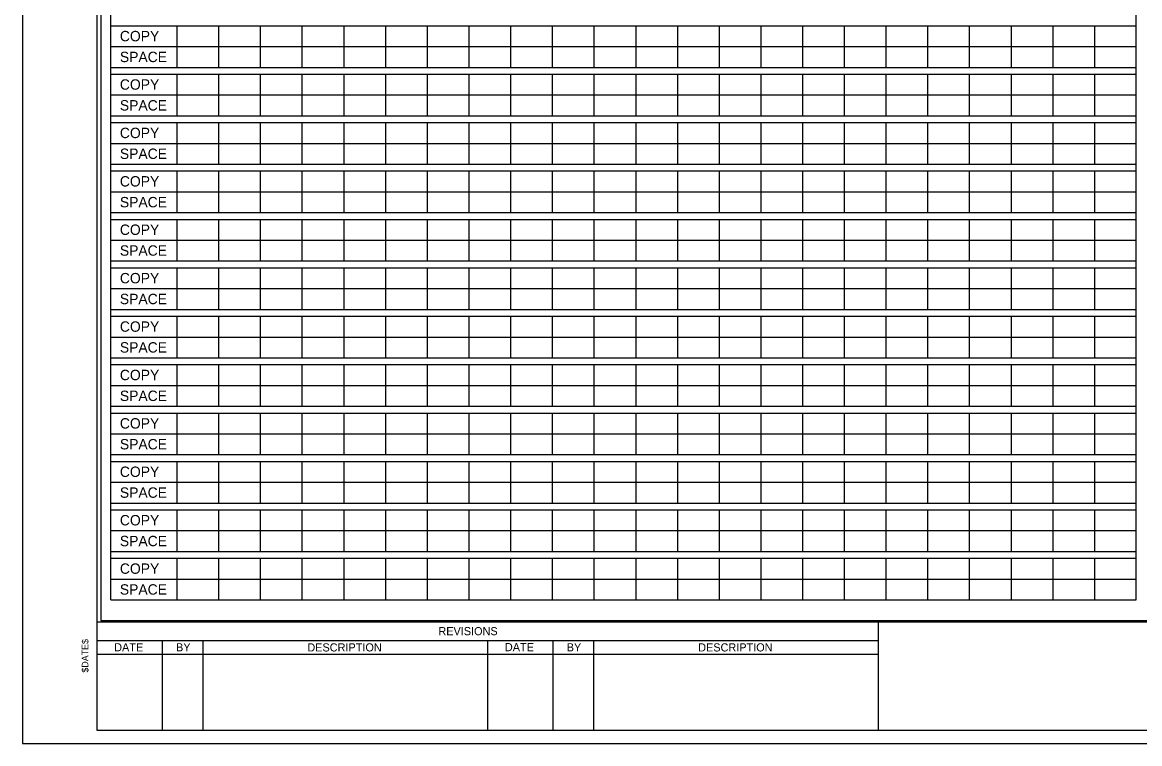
# Model space of a CAD drawing. Extents: x 17890459 to 17890580, y 17897938 to 17898017.
# Drawn here: x 17890458.9 to 17890519.4, y 17897939.5 to 17897978.6 of the extents above; entities that cross this region are included whole.
import ezdxf

# ---------------------------------------------------------------- set-up
doc = ezdxf.new("R2010")
doc.units = 0
for name, color, linetype in [('PlotBorder_dp', 7, 'Continuous'), ('SheetBorder_dp', 7, 'Continuous'), ('SheetLines_dp', 7, 'Continuous'), ('SheetLinesMisc2_dp', 7, 'Continuous'), ('TextMinor', 7, 'Continuous'), ('TextMisc', 7, 'Continuous')]:
    doc.layers.add(name, color=color, linetype=linetype)

msp = doc.modelspace()

# ---------------------------------------------------------------- linework, layer by layer
at = {"layer": 'PlotBorder_dp'}
msp.add_lwpolyline([(17890458.908, 17897939.544), (17890580.045, 17897939.544), (17890580.045, 17898017.365), (17890458.908, 17898017.365)], close=True, dxfattribs=at)
at = {"layer": 'SheetBorder_dp'}
for p, q in [((17890462.946, 17898016.631), (17890462.946, 17897940.278)), ((17890462.946, 17897946.151), (17890576.007, 17897946.151)), ((17890462.946, 17897940.278), (17890576.007, 17897940.278))]:
    msp.add_line(p, q, dxfattribs=at)
at = {"layer": 'SheetLines_dp'}
for p, q in [((17890505.233, 17897946.151), (17890505.233, 17897940.278)), ((17890462.946, 17897945.123), (17890505.233, 17897945.123)), ((17890466.47, 17897945.123), (17890466.47, 17897940.278)), ((17890468.672, 17897945.123), (17890468.672, 17897940.278)), ((17890484.09, 17897945.123), (17890484.09, 17897940.278)), ((17890487.614, 17897945.123), (17890487.614, 17897940.278)), ((17890489.816, 17897945.123), (17890489.816, 17897940.278)), ((17890462.946, 17897944.389), (17890505.233, 17897944.389))]:
    msp.add_line(p, q, dxfattribs=at)
at = {"layer": 'SheetLinesMisc2_dp'}
for p, q in [((17890463.151, 17898016.456), (17890463.151, 17897946.221)), ((17890463.699, 17897947.331), (17890463.699, 17897991.536)), ((17890519.188, 17897947.331), (17890519.188, 17897991.536)), ((17890463.699, 17897978.426), (17890519.188, 17897978.426)), ((17890467.271, 17897978.426), (17890467.271, 17897976.172)), ((17890469.528, 17897978.426), (17890469.528, 17897976.172)), ((17890471.786, 17897978.426), (17890471.786, 17897976.172)), ((17890474.042, 17897978.426), (17890474.042, 17897976.172)), ((17890476.3, 17897978.426), (17890476.3, 17897976.172)), ((17890478.557, 17897978.426), (17890478.557, 17897976.172)), ((17890480.815, 17897978.426), (17890480.815, 17897976.172)), ((17890483.072, 17897978.426), (17890483.072, 17897976.172)), ((17890485.329, 17897978.426), (17890485.329, 17897976.172)), ((17890487.586, 17897978.426), (17890487.586, 17897976.172)), ((17890489.844, 17897978.426), (17890489.844, 17897976.172)), ((17890492.101, 17897978.426), (17890492.101, 17897976.172)), ((17890494.358, 17897978.426), (17890494.358, 17897976.172)), ((17890496.615, 17897978.426), (17890496.615, 17897976.172)), ((17890498.873, 17897978.426), (17890498.873, 17897976.172)), ((17890501.13, 17897978.426), (17890501.13, 17897976.172)), ((17890503.387, 17897978.426), (17890503.387, 17897976.172)), ((17890505.644, 17897978.426), (17890505.644, 17897976.172)), ((17890507.902, 17897978.426), (17890507.902, 17897976.172)), ((17890510.159, 17897978.426), (17890510.159, 17897976.172)), ((17890512.416, 17897978.426), (17890512.416, 17897976.172)), ((17890514.673, 17897978.426), (17890514.673, 17897976.172)), ((17890516.931, 17897978.426), (17890516.931, 17897976.172)), ((17890463.699, 17897977.299), (17890519.188, 17897977.299)), ((17890463.699, 17897976.172), (17890519.188, 17897976.172)), ((17890463.699, 17897975.804), (17890519.188, 17897975.804)), ((17890467.271, 17897975.804), (17890467.271, 17897973.55)), ((17890469.528, 17897975.804), (17890469.528, 17897973.55)), ((17890471.786, 17897975.804), (17890471.786, 17897973.55)), ((17890474.042, 17897975.804), (17890474.042, 17897973.55)), ((17890476.3, 17897975.804), (17890476.3, 17897973.55)), ((17890478.557, 17897975.804), (17890478.557, 17897973.55)), ((17890480.815, 17897975.804), (17890480.815, 17897973.55)), ((17890483.072, 17897975.804), (17890483.072, 17897973.55)), ((17890485.329, 17897975.804), (17890485.329, 17897973.55)), ((17890487.586, 17897975.804), (17890487.586, 17897973.55)), ((17890489.844, 17897975.804), (17890489.844, 17897973.55)), ((17890492.101, 17897975.804), (17890492.101, 17897973.55)), ((17890494.358, 17897975.804), (17890494.358, 17897973.55)), ((17890496.615, 17897975.804), (17890496.615, 17897973.55)), ((17890498.873, 17897975.804), (17890498.873, 17897973.55)), ((17890501.13, 17897975.804), (17890501.13, 17897973.55)), ((17890503.387, 17897975.804), (17890503.387, 17897973.55)), ((17890505.644, 17897975.804), (17890505.644, 17897973.55)), ((17890507.902, 17897975.804), (17890507.902, 17897973.55)), ((17890510.159, 17897975.804), (17890510.159, 17897973.55)), ((17890512.416, 17897975.804), (17890512.416, 17897973.55)), ((17890514.673, 17897975.804), (17890514.673, 17897973.55)), ((17890516.931, 17897975.804), (17890516.931, 17897973.55)), ((17890463.699, 17897974.677), (17890519.188, 17897974.677)), ((17890463.699, 17897973.55), (17890519.188, 17897973.55)), ((17890463.699, 17897973.182), (17890519.188, 17897973.182)), ((17890467.271, 17897973.182), (17890467.271, 17897970.928)), ((17890469.528, 17897973.182), (17890469.528, 17897970.928)), ((17890471.786, 17897973.182), (17890471.786, 17897970.928)), ((17890474.042, 17897973.182), (17890474.042, 17897970.928)), ((17890476.3, 17897973.182), (17890476.3, 17897970.928)), ((17890478.557, 17897973.182), (17890478.557, 17897970.928)), ((17890480.815, 17897973.182), (17890480.815, 17897970.928)), ((17890483.072, 17897973.182), (17890483.072, 17897970.928)), ((17890485.329, 17897973.182), (17890485.329, 17897970.928)), ((17890487.586, 17897973.182), (17890487.586, 17897970.928)), ((17890489.844, 17897973.182), (17890489.844, 17897970.928)), ((17890492.101, 17897973.182), (17890492.101, 17897970.928)), ((17890494.358, 17897973.182), (17890494.358, 17897970.928)), ((17890496.615, 17897973.182), (17890496.615, 17897970.928)), ((17890498.873, 17897973.182), (17890498.873, 17897970.928)), ((17890501.13, 17897973.182), (17890501.13, 17897970.928)), ((17890503.387, 17897973.182), (17890503.387, 17897970.928)), ((17890505.644, 17897973.182), (17890505.644, 17897970.928)), ((17890507.902, 17897973.182), (17890507.902, 17897970.928)), ((17890510.159, 17897973.182), (17890510.159, 17897970.928)), ((17890512.416, 17897973.182), (17890512.416, 17897970.928)), ((17890514.673, 17897973.182), (17890514.673, 17897970.928)), ((17890516.931, 17897973.182), (17890516.931, 17897970.928)), ((17890463.699, 17897972.055), (17890519.188, 17897972.055)), ((17890463.699, 17897970.928), (17890519.188, 17897970.928)), ((17890463.699, 17897970.56), (17890519.188, 17897970.56)), ((17890467.271, 17897970.56), (17890467.271, 17897968.306)), ((17890469.528, 17897970.56), (17890469.528, 17897968.306)), ((17890471.786, 17897970.56), (17890471.786, 17897968.306)), ((17890474.042, 17897970.56), (17890474.042, 17897968.306)), ((17890476.3, 17897970.56), (17890476.3, 17897968.306)), ((17890478.557, 17897970.56), (17890478.557, 17897968.306)), ((17890480.815, 17897970.56), (17890480.815, 17897968.306)), ((17890483.072, 17897970.56), (17890483.072, 17897968.306)), ((17890485.329, 17897970.56), (17890485.329, 17897968.306)), ((17890487.586, 17897970.56), (17890487.586, 17897968.306)), ((17890489.844, 17897970.56), (17890489.844, 17897968.306)), ((17890492.101, 17897970.56), (17890492.101, 17897968.306)), ((17890494.358, 17897970.56), (17890494.358, 17897968.306)), ((17890496.615, 17897970.56), (17890496.615, 17897968.306)), ((17890498.873, 17897970.56), (17890498.873, 17897968.306)), ((17890501.13, 17897970.56), (17890501.13, 17897968.306)), ((17890503.387, 17897970.56), (17890503.387, 17897968.306)), ((17890505.644, 17897970.56), (17890505.644, 17897968.306)), ((17890507.902, 17897970.56), (17890507.902, 17897968.306)), ((17890510.159, 17897970.56), (17890510.159, 17897968.306)), ((17890512.416, 17897970.56), (17890512.416, 17897968.306)), ((17890514.673, 17897970.56), (17890514.673, 17897968.306)), ((17890516.931, 17897970.56), (17890516.931, 17897968.306)), ((17890463.699, 17897969.434), (17890519.188, 17897969.434)), ((17890463.699, 17897968.306), (17890519.188, 17897968.306)), ((17890463.699, 17897967.939), (17890519.188, 17897967.939)), ((17890467.271, 17897967.939), (17890467.271, 17897965.685)), ((17890469.528, 17897967.939), (17890469.528, 17897965.685)), ((17890471.786, 17897967.939), (17890471.786, 17897965.685)), ((17890474.042, 17897967.939), (17890474.042, 17897965.685)), ((17890476.3, 17897967.939), (17890476.3, 17897965.685)), ((17890478.557, 17897967.939), (17890478.557, 17897965.685)), ((17890480.815, 17897967.939), (17890480.815, 17897965.685)), ((17890483.072, 17897967.939), (17890483.072, 17897965.685)), ((17890485.329, 17897967.939), (17890485.329, 17897965.685)), ((17890487.586, 17897967.939), (17890487.586, 17897965.685)), ((17890489.844, 17897967.939), (17890489.844, 17897965.685)), ((17890492.101, 17897967.939), (17890492.101, 17897965.685)), ((17890494.358, 17897967.939), (17890494.358, 17897965.685)), ((17890496.615, 17897967.939), (17890496.615, 17897965.685)), ((17890498.873, 17897967.939), (17890498.873, 17897965.685)), ((17890501.13, 17897967.939), (17890501.13, 17897965.685)), ((17890503.387, 17897967.939), (17890503.387, 17897965.685)), ((17890505.644, 17897967.939), (17890505.644, 17897965.685)), ((17890507.902, 17897967.939), (17890507.902, 17897965.685)), ((17890510.159, 17897967.939), (17890510.159, 17897965.685)), ((17890512.416, 17897967.939), (17890512.416, 17897965.685)), ((17890514.673, 17897967.939), (17890514.673, 17897965.685)), ((17890516.931, 17897967.939), (17890516.931, 17897965.685)), ((17890463.699, 17897966.811), (17890519.188, 17897966.812)), ((17890463.699, 17897965.685), (17890519.188, 17897965.685)), ((17890463.699, 17897965.317), (17890519.188, 17897965.317)), ((17890467.271, 17897965.317), (17890467.271, 17897963.063)), ((17890469.528, 17897965.317), (17890469.528, 17897963.063)), ((17890471.786, 17897965.317), (17890471.786, 17897963.063)), ((17890474.042, 17897965.317), (17890474.042, 17897963.063)), ((17890476.3, 17897965.317), (17890476.3, 17897963.063)), ((17890478.557, 17897965.317), (17890478.557, 17897963.063)), ((17890480.815, 17897965.317), (17890480.815, 17897963.063)), ((17890483.072, 17897965.317), (17890483.072, 17897963.063)), ((17890485.329, 17897965.317), (17890485.329, 17897963.063)), ((17890487.586, 17897965.317), (17890487.586, 17897963.063)), ((17890489.844, 17897965.317), (17890489.844, 17897963.063)), ((17890492.101, 17897965.317), (17890492.101, 17897963.063)), ((17890494.358, 17897965.317), (17890494.358, 17897963.063)), ((17890496.615, 17897965.317), (17890496.615, 17897963.063)), ((17890498.873, 17897965.317), (17890498.873, 17897963.063)), ((17890501.13, 17897965.317), (17890501.13, 17897963.063)), ((17890503.387, 17897965.317), (17890503.387, 17897963.063)), ((17890505.644, 17897965.317), (17890505.644, 17897963.063)), ((17890507.902, 17897965.317), (17890507.902, 17897963.063)), ((17890510.159, 17897965.317), (17890510.159, 17897963.063)), ((17890512.416, 17897965.317), (17890512.416, 17897963.063)), ((17890514.673, 17897965.317), (17890514.673, 17897963.063)), ((17890516.931, 17897965.317), (17890516.931, 17897963.063)), ((17890463.699, 17897964.189), (17890519.188, 17897964.189)), ((17890463.699, 17897963.063), (17890519.188, 17897963.063)), ((17890463.699, 17897962.695), (17890519.188, 17897962.695)), ((17890467.271, 17897962.695), (17890467.271, 17897960.44)), ((17890469.528, 17897962.695), (17890469.528, 17897960.44)), ((17890471.786, 17897962.695), (17890471.786, 17897960.44)), ((17890474.042, 17897962.695), (17890474.042, 17897960.44)), ((17890476.3, 17897962.695), (17890476.3, 17897960.44)), ((17890478.557, 17897962.695), (17890478.557, 17897960.44)), ((17890480.815, 17897962.695), (17890480.815, 17897960.44)), ((17890483.072, 17897962.695), (17890483.072, 17897960.44)), ((17890485.329, 17897962.695), (17890485.329, 17897960.44)), ((17890487.586, 17897962.695), (17890487.586, 17897960.44)), ((17890489.844, 17897962.695), (17890489.844, 17897960.44)), ((17890492.101, 17897962.695), (17890492.101, 17897960.44)), ((17890494.358, 17897962.695), (17890494.358, 17897960.44)), ((17890496.615, 17897962.695), (17890496.615, 17897960.44)), ((17890498.873, 17897962.695), (17890498.873, 17897960.44)), ((17890501.13, 17897962.695), (17890501.13, 17897960.44)), ((17890503.387, 17897962.695), (17890503.387, 17897960.44)), ((17890505.644, 17897962.695), (17890505.644, 17897960.44)), ((17890507.902, 17897962.695), (17890507.902, 17897960.44)), ((17890510.159, 17897962.695), (17890510.159, 17897960.44)), ((17890512.416, 17897962.695), (17890512.416, 17897960.44)), ((17890514.673, 17897962.695), (17890514.673, 17897960.44)), ((17890516.931, 17897962.695), (17890516.931, 17897960.44)), ((17890463.699, 17897961.568), (17890519.188, 17897961.568)), ((17890463.699, 17897960.44), (17890519.188, 17897960.44)), ((17890463.699, 17897960.073), (17890519.188, 17897960.073)), ((17890467.271, 17897960.073), (17890467.271, 17897957.819)), ((17890469.528, 17897960.073), (17890469.528, 17897957.819)), ((17890471.786, 17897960.073), (17890471.786, 17897957.819)), ((17890474.042, 17897960.073), (17890474.042, 17897957.819)), ((17890476.3, 17897960.073), (17890476.3, 17897957.819)), ((17890478.557, 17897960.073), (17890478.557, 17897957.819)), ((17890480.815, 17897960.073), (17890480.815, 17897957.819)), ((17890483.072, 17897960.073), (17890483.072, 17897957.819)), ((17890485.329, 17897960.073), (17890485.329, 17897957.819)), ((17890487.586, 17897960.073), (17890487.586, 17897957.819)), ((17890489.844, 17897960.073), (17890489.844, 17897957.819)), ((17890492.101, 17897960.073), (17890492.101, 17897957.819)), ((17890494.358, 17897960.073), (17890494.358, 17897957.819)), ((17890496.615, 17897960.073), (17890496.615, 17897957.819)), ((17890498.873, 17897960.073), (17890498.873, 17897957.819)), ((17890501.13, 17897960.073), (17890501.13, 17897957.819)), ((17890503.387, 17897960.073), (17890503.387, 17897957.819)), ((17890505.644, 17897960.073), (17890505.644, 17897957.819)), ((17890507.902, 17897960.073), (17890507.902, 17897957.819)), ((17890510.159, 17897960.073), (17890510.159, 17897957.819)), ((17890512.416, 17897960.073), (17890512.416, 17897957.819)), ((17890514.673, 17897960.073), (17890514.673, 17897957.819)), ((17890516.931, 17897960.073), (17890516.931, 17897957.819)), ((17890463.699, 17897958.946), (17890519.188, 17897958.946)), ((17890463.699, 17897957.819), (17890519.188, 17897957.819)), ((17890463.699, 17897957.451), (17890519.188, 17897957.451)), ((17890467.271, 17897957.451), (17890467.271, 17897955.197)), ((17890469.528, 17897957.451), (17890469.528, 17897955.197)), ((17890471.786, 17897957.451), (17890471.786, 17897955.197)), ((17890474.042, 17897957.451), (17890474.042, 17897955.197)), ((17890476.3, 17897957.451), (17890476.3, 17897955.197)), ((17890478.557, 17897957.451), (17890478.557, 17897955.197)), ((17890480.815, 17897957.451), (17890480.815, 17897955.197)), ((17890483.072, 17897957.451), (17890483.072, 17897955.197)), ((17890485.329, 17897957.451), (17890485.329, 17897955.197)), ((17890487.586, 17897957.451), (17890487.586, 17897955.197)), ((17890489.844, 17897957.451), (17890489.844, 17897955.197)), ((17890492.101, 17897957.451), (17890492.101, 17897955.197)), ((17890494.358, 17897957.451), (17890494.358, 17897955.197)), ((17890496.615, 17897957.451), (17890496.615, 17897955.197)), ((17890498.873, 17897957.451), (17890498.873, 17897955.197)), ((17890501.13, 17897957.451), (17890501.13, 17897955.197)), ((17890503.387, 17897957.451), (17890503.387, 17897955.197)), ((17890505.644, 17897957.451), (17890505.644, 17897955.197)), ((17890507.902, 17897957.451), (17890507.902, 17897955.197)), ((17890510.159, 17897957.451), (17890510.159, 17897955.197)), ((17890512.416, 17897957.451), (17890512.416, 17897955.197)), ((17890514.673, 17897957.451), (17890514.673, 17897955.197)), ((17890516.931, 17897957.451), (17890516.931, 17897955.197)), ((17890463.699, 17897956.324), (17890519.188, 17897956.324)), ((17890463.699, 17897955.197), (17890519.188, 17897955.197)), ((17890463.699, 17897954.829), (17890519.188, 17897954.829)), ((17890467.271, 17897954.829), (17890467.271, 17897952.575)), ((17890469.528, 17897954.829), (17890469.528, 17897952.575)), ((17890471.786, 17897954.829), (17890471.786, 17897952.575)), ((17890474.042, 17897954.829), (17890474.042, 17897952.575)), ((17890476.3, 17897954.829), (17890476.3, 17897952.575)), ((17890478.557, 17897954.829), (17890478.557, 17897952.575)), ((17890480.815, 17897954.829), (17890480.815, 17897952.575)), ((17890483.072, 17897954.829), (17890483.072, 17897952.575)), ((17890485.329, 17897954.829), (17890485.329, 17897952.575)), ((17890487.586, 17897954.829), (17890487.586, 17897952.575)), ((17890489.844, 17897954.829), (17890489.844, 17897952.575)), ((17890492.101, 17897954.829), (17890492.101, 17897952.575)), ((17890494.358, 17897954.829), (17890494.358, 17897952.575)), ((17890496.615, 17897954.829), (17890496.615, 17897952.575)), ((17890498.873, 17897954.829), (17890498.873, 17897952.575)), ((17890501.13, 17897954.829), (17890501.13, 17897952.575)), ((17890503.387, 17897954.829), (17890503.387, 17897952.575)), ((17890505.644, 17897954.829), (17890505.644, 17897952.575)), ((17890507.902, 17897954.829), (17890507.902, 17897952.575)), ((17890510.159, 17897954.829), (17890510.159, 17897952.575)), ((17890512.416, 17897954.829), (17890512.416, 17897952.575)), ((17890514.673, 17897954.829), (17890514.673, 17897952.575)), ((17890516.931, 17897954.829), (17890516.931, 17897952.575)), ((17890463.699, 17897953.702), (17890519.188, 17897953.702)), ((17890463.699, 17897952.575), (17890519.188, 17897952.575)), ((17890463.699, 17897952.208), (17890519.188, 17897952.208)), ((17890467.271, 17897952.208), (17890467.271, 17897949.953)), ((17890469.528, 17897952.208), (17890469.528, 17897949.953)), ((17890471.786, 17897952.208), (17890471.786, 17897949.953)), ((17890474.042, 17897952.208), (17890474.042, 17897949.953)), ((17890476.3, 17897952.208), (17890476.3, 17897949.953)), ((17890478.557, 17897952.208), (17890478.557, 17897949.953)), ((17890480.815, 17897952.208), (17890480.815, 17897949.953)), ((17890483.072, 17897952.208), (17890483.072, 17897949.953)), ((17890485.329, 17897952.208), (17890485.329, 17897949.953)), ((17890487.586, 17897952.208), (17890487.586, 17897949.953)), ((17890489.844, 17897952.208), (17890489.844, 17897949.953)), ((17890492.101, 17897952.208), (17890492.101, 17897949.953)), ((17890494.358, 17897952.208), (17890494.358, 17897949.953)), ((17890496.615, 17897952.208), (17890496.615, 17897949.953)), ((17890498.873, 17897952.208), (17890498.873, 17897949.953)), ((17890501.13, 17897952.208), (17890501.13, 17897949.953)), ((17890503.387, 17897952.208), (17890503.387, 17897949.953)), ((17890505.644, 17897952.208), (17890505.644, 17897949.953)), ((17890507.902, 17897952.208), (17890507.902, 17897949.953)), ((17890510.159, 17897952.208), (17890510.159, 17897949.953)), ((17890512.416, 17897952.208), (17890512.416, 17897949.953)), ((17890514.673, 17897952.208), (17890514.673, 17897949.953)), ((17890516.931, 17897952.208), (17890516.931, 17897949.953)), ((17890463.699, 17897951.08), (17890519.188, 17897951.08)), ((17890463.699, 17897949.953), (17890519.188, 17897949.953)), ((17890463.699, 17897949.586), (17890519.188, 17897949.586)), ((17890467.271, 17897949.586), (17890467.271, 17897947.331)), ((17890469.528, 17897949.586), (17890469.528, 17897947.331)), ((17890471.786, 17897949.586), (17890471.786, 17897947.331)), ((17890474.042, 17897949.586), (17890474.042, 17897947.331)), ((17890476.3, 17897949.586), (17890476.3, 17897947.331)), ((17890478.557, 17897949.586), (17890478.557, 17897947.331)), ((17890480.815, 17897949.586), (17890480.815, 17897947.331)), ((17890483.072, 17897949.586), (17890483.072, 17897947.331)), ((17890485.329, 17897949.586), (17890485.329, 17897947.331)), ((17890487.586, 17897949.586), (17890487.586, 17897947.331)), ((17890489.844, 17897949.586), (17890489.844, 17897947.331)), ((17890492.101, 17897949.586), (17890492.101, 17897947.331)), ((17890494.358, 17897949.586), (17890494.358, 17897947.331)), ((17890496.615, 17897949.586), (17890496.615, 17897947.331)), ((17890498.873, 17897949.586), (17890498.873, 17897947.331)), ((17890501.13, 17897949.586), (17890501.13, 17897947.331)), ((17890503.387, 17897949.586), (17890503.387, 17897947.331)), ((17890505.644, 17897949.586), (17890505.644, 17897947.331)), ((17890507.902, 17897949.586), (17890507.902, 17897947.331)), ((17890510.159, 17897949.586), (17890510.159, 17897947.331)), ((17890512.416, 17897949.586), (17890512.416, 17897947.331)), ((17890514.673, 17897949.586), (17890514.673, 17897947.331)), ((17890516.931, 17897949.586), (17890516.931, 17897947.331)), ((17890463.699, 17897948.458), (17890519.188, 17897948.458)), ((17890463.699, 17897947.331), (17890519.188, 17897947.331)), ((17890463.151, 17897946.221), (17890575.98, 17897946.221))]:
    msp.add_line(p, q, dxfattribs=at)

# ---------------------------------------------------------------- texts
at = {"layer": 'TextMinor'}
for s, p in [('COPY', (17890464.186, 17897977.583)), ('SPACE', (17890464.186, 17897976.456)), ('COPY', (17890464.186, 17897974.961)), ('SPACE', (17890464.186, 17897973.834)), ('COPY', (17890464.186, 17897972.339)), ('SPACE', (17890464.186, 17897971.211)), ('COPY', (17890464.186, 17897969.718)), ('SPACE', (17890464.186, 17897968.59)), ('COPY', (17890464.186, 17897967.098)), ('SPACE', (17890464.186, 17897965.971)), ('COPY', (17890464.186, 17897964.474)), ('SPACE', (17890464.186, 17897963.346)), ('COPY', (17890464.186, 17897961.852)), ('SPACE', (17890464.186, 17897960.725)), ('COPY', (17890464.186, 17897959.23)), ('SPACE', (17890464.186, 17897958.102)), ('COPY', (17890464.186, 17897956.609)), ('SPACE', (17890464.186, 17897955.481)), ('COPY', (17890464.186, 17897953.989)), ('SPACE', (17890464.186, 17897952.861)), ('COPY', (17890464.186, 17897951.364)), ('SPACE', (17890464.186, 17897950.237)), ('COPY', (17890464.186, 17897948.743)), ('SPACE', (17890464.186, 17897947.615))]:
    msp.add_text(s, height=0.5625, dxfattribs=at).set_placement(p)
msp.add_text('$DATE$', height=0.3598, rotation=90, dxfattribs=at).set_placement((17890462.483, 17897943.392))
at = {"layer": 'TextMisc'}
for s, p in [('REVISIONS', (17890481.425, 17897945.417)), ('BY', (17890467.226, 17897944.543)), ('BY', (17890488.37, 17897944.543))]:
    msp.add_text(s, height=0.4405, dxfattribs=at).set_placement(p)
for s, height, rotation, p in [('DATE', 0.4405, 359.86925, (17890463.878, 17897944.543)), ('DESCRIPTION', 0.44041, 0.04975, (17890474.333, 17897944.536)), ('DATE', 0.4405, 359.86925, (17890485.022, 17897944.551)), ('DESCRIPTION', 0.44041, 0.04975, (17890495.484, 17897944.536))]:
    msp.add_text(s, height=height, rotation=rotation, dxfattribs=at).set_placement(p)

doc.saveas('drawing.dxf')
